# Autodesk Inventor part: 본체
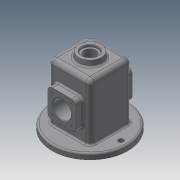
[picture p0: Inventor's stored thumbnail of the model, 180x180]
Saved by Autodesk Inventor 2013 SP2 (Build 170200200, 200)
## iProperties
Created: 2021-08
Part Number: 본체
Material: Generic
Document SubType Name: Modeling
Designer: kumco
Density: 1 g/cm^3
Author: kumco
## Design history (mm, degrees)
sketch "스케치1"
  geometry: L1 (-37, -37)-(37, -37); L2 (37, -37)-(37, 37); L3 (37, 37)-(-37, 37); L4 (-37, 37)-(-37, -37); L5 (-37, -37)-(37, 37); L6 (37, -37)-(-37, 37); 1 further point
  constraints: 12 end point, 2 midpoint, 2 parallel, 1 horizontal, 1 perpendicular
  dimensions: "d0" = 74 distance of L3.end L2.end; "d1" = 74 distance of L2.end L1.end
extrude "돌출1" new body sketch "스케치1" distance "d2" = 110; taper "d3" = 0 deg
fillet "모깎기1" dims "d4" = 8
fillet "모깎기2" dims "d5" = 8
feature "쉘1" dims "d6" = 5
sketch "스케치2"
  geometry: L1 (29, -37)-(-29, -37) reference; L2 (37, 29)-(37, -29) reference; L3 (-29, 37)-(29, 37) reference; L4 (-37, -29)-(-37, 29) reference; C1 r 67 at (0, 0); A1 r 8 centre (-29, -29) between (-37, -29) and (-29, -37) reference; A2 r 8 centre (29, -29) between (29, -37) and (37, -29) reference; A3 r 8 centre (29, 29) between (37, 29) and (29, 37) reference; A4 r 8 centre (-29, 29) between (-29, 37) and (-37, 29) reference; 1 further point
  constraints: 1 centre point, 1 coincident
  dimensions: "d7" = 134 diameter of C1
extrude "돌출2" join sketch "스케치2" distance "d9" = 10; taper "d10" = 0 deg
sketch "스케치3"
  geometry: L1 (58, 0)-(58, 102) reference; L2 (29, 0)-(29, 55); C1 r 25 at (29, 55)
  constraints: 2 end point, 1 centre point, 1 coincident, 1 parallel
  dimensions: "d11" = 55 distance of L2.start L2.end; "d12" = 50 diameter of C1
extrude "돌출3" join sketch "스케치3" distance "d13" = 7; taper "d14" = -20 deg
sketch "스케치4"
  geometry: L1 (0, -92)-(0, 0) reference; L2 (29, -102)-(29, -47); L3 (54, -72)-(4, -72); L4 (4, -72)-(4, -22); L5 (4, -22)-(54, -22); L6 (54, -22)-(54, -72); L7 (54, -72)-(4, -22); L8 (4, -72)-(54, -22)
  constraints: 14 end point, 3 parallel, 2 midpoint, 1 horizontal, 1 perpendicular
  dimensions: "d15" = 55 distance of L2.start L2.end; "d16" = 50 distance of L4.end L5.end; "d17" = 50 distance of L3.end L4.end
extrude "돌출4" join sketch "스케치4" distance "d18" = 13; taper "d19" = 0 deg
sketch "스케치5"
  geometry: C1 r 22.452 at (29, -47) reference; C2 r 16 at (29, -47); 1 further point
  constraints: 1 centre point, 1 coincident
  dimensions: "d20" = 32 diameter of C2
extrude "돌출5" cut sketch "스케치5" stored distance "d21" = 13; taper "d22" = 0 deg
sketch "스케치6"
  geometry: L1 (46, -64)-(12, -64); L2 (12, -64)-(12, -30); L3 (12, -30)-(46, -30); L4 (46, -30)-(46, -64); L5 (46, -64)-(12, -30); L6 (12, -64)-(46, -30); C1 r 16 at (29, -47) reference; 5 further points
  constraints: 12 end point, 4 coincident, 2 midpoint, 2 parallel, 1 horizontal, 1 perpendicular
  dimensions: "d23" = 34 distance of L2.end L3.end; "d24" = 34 distance of L1.end L2.end
hole "구멍1" sketch "스케치6" at (12, -30), (46, -30), (46, -64), (12, -64) diameter "d25" = 3.242; stored, may be unused: countersink angle "d29" = 90 deg, drill point angle "d31" = 118 deg; dims "d26" = 8, "d27" = 4, "d28" = 2, "d30" = 10
sketch "스케치7"
  geometry: C1 r 67 at (0, 0) reference; A1 r 55 centre (0, 0) between (0, 55) and (0, -55)
  constraints: 2 point on circle, 1 centre point, 1 coincident
  dimensions: "d32" = 110 diameter of A1
hole "구멍2" sketch "스케치7" at (0, 55), (0, -55) diameter "d33" = 9; stored, may be unused: countersink angle "d37" = 90 deg, drill point angle "d39" = 118 deg; dims "d34" = 8, "d35" = 4, "d36" = 2, "d38" = 10
node "작업 평면1"
sketch "스케치8"
  geometry: C1 r 20 at (0, 0); 1 further point
  constraints: 1 centre point, 1 coincident
  dimensions: "d41" = 40 diameter of C1
extrude "돌출6" join sketch "스케치8" stored distance "d42" = 40 (= d41); taper "d43" = 6 deg
sketch "스케치9"
  geometry: C1 r 20 at (0, 0) reference; C2 r 14 at (0, 0)
  constraints: 1 centre point, 1 coincident
  dimensions: "d44" = 28 diameter of C2
extrude "돌출7" cut sketch "스케치9" distance "d45" = 4; taper "d46" = 0 deg
sketch "스케치10"
  geometry: C1 r 14 at (0, 0) reference; C2 r 10.5 at (0, 0)
  constraints: 1 centre point, 1 coincident
  dimensions: "d47" = 21 diameter of C2
extrude "돌출8" cut sketch "스케치10" stored distance "d48" = 4; taper "d49" = 0 deg
sketch "스케치11"
  geometry: L1 (-8, 0)-(-8, -92) reference; L2 (9, 18)-(49, 18) reference; 2 further points
  constraints: 1 other
  dimensions: "d50" = 37 distance from line of point (29, -10) L1; "d51" = 28 distance from line of point (29, -10) L2
feature "엠보싱1" sketch "스케치11" dims "d0" = 74, "d1" = 74, "d52" = 0.5, "d53" = 0
fillet "모깎기3" dims "d54" = 8
fillet "모깎기4" dims "d55" = 3
fillet "모깎기5" dims "d56" = 3
chamfer "모따기1" distance "d57" = 1; stored, may be unused: second distance "d58" = 2, angle "d59" = 45 deg
fillet "모깎기6" dims "d60" = 3
node "솔리드1"
mirror "대칭1"
mirror "대칭2"
